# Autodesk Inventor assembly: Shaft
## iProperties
Created: 2007-11
Part Number: Shaft
Document SubType Name: Assembly
Designer: CM
Mass: 744.543 g
Surface Area: 152.39 cm^2
Volume: 94.8463 cm^3
Density: 7.85 g/cm^3
ClientObjectVersion: 1
Author: CM
